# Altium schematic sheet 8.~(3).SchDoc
size 420 x 297 mm
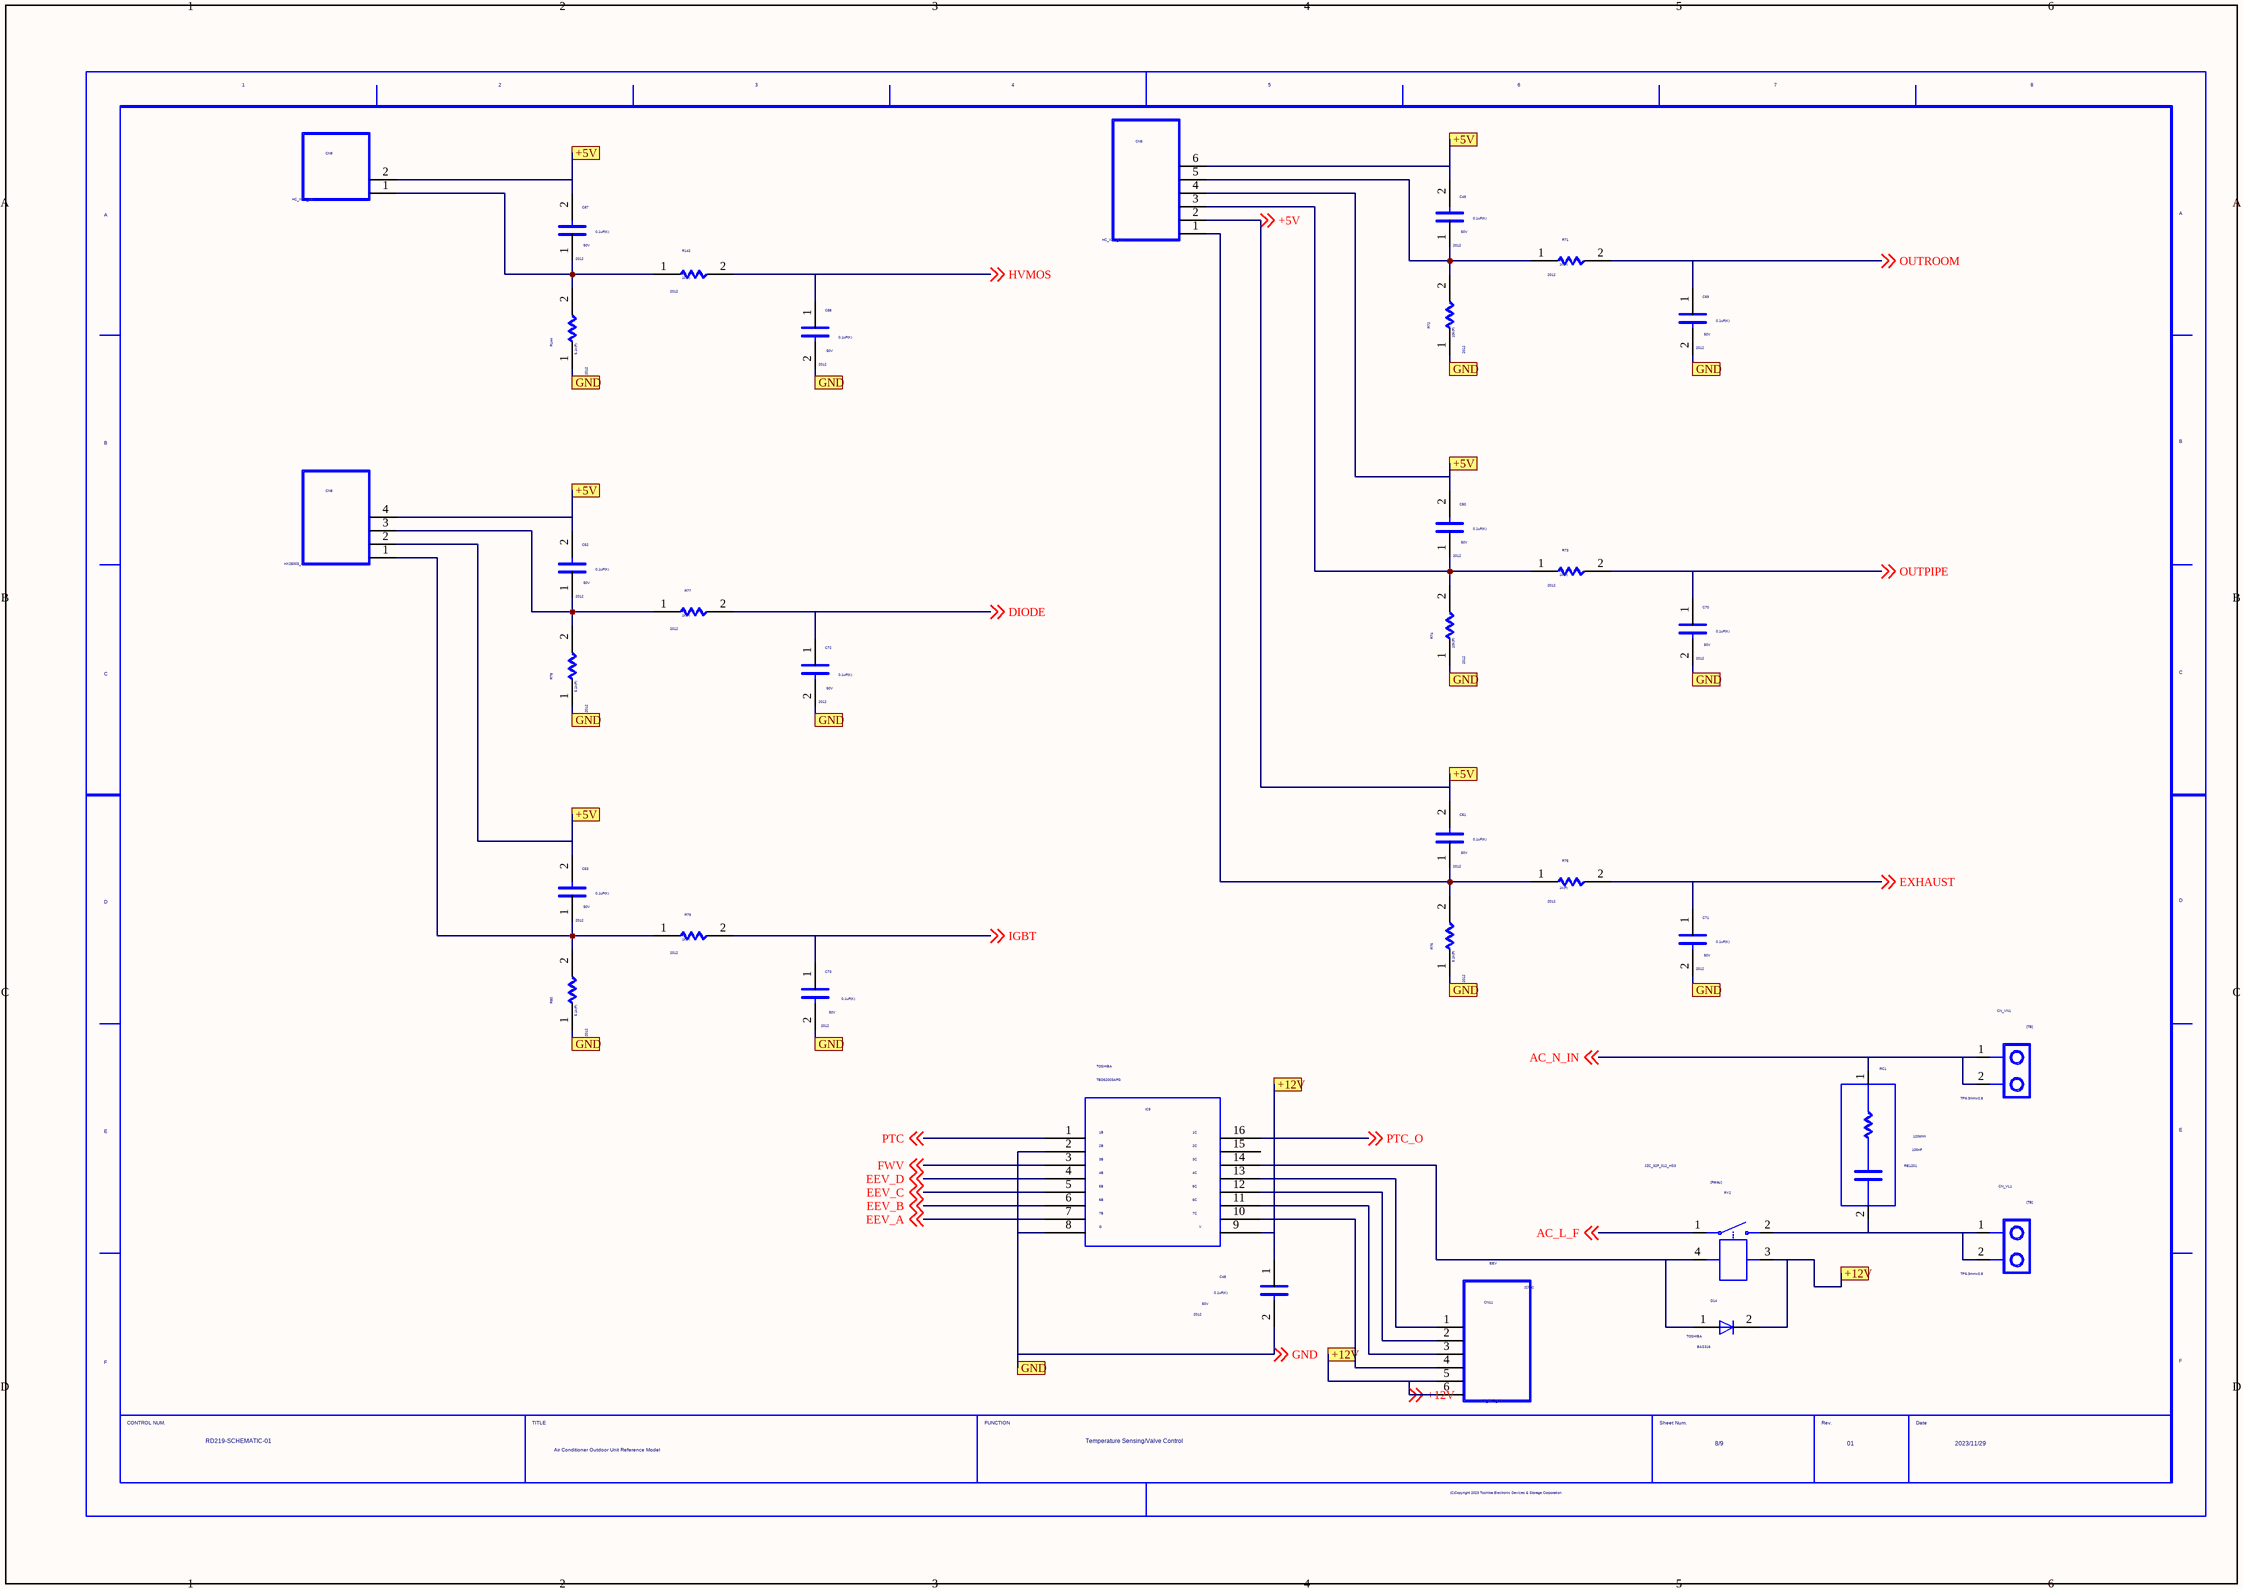
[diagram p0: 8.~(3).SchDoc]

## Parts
C48  SIZECODESMD: 2012  VAL2: 50V  VAL1: 0.1uF(K)  (hidden comment: C)
C49  SIZECODESMD: 2012  VAL2: 50V  VAL1: 0.1uF(K)  (hidden comment: C)
C50  SIZECODESMD: 2012  VAL2: 50V  VAL1: 0.1uF(K)  (hidden comment: C)
C51  SIZECODESMD: 2012  VAL2: 50V  VAL1: 0.1uF(K)  (hidden comment: C)
C52  SIZECODESMD: 2012  VAL2: 50V  VAL1: 0.1uF(K)  (hidden comment: C)
C53  SIZECODESMD: 2012  VAL2: 50V  VAL1: 0.1uF(K)  (hidden comment: C)
C69  SIZECODESMD: 2012  VAL2: 50V  VAL1: 0.1uF(K)  (hidden comment: C)
C70  SIZECODESMD: 2012  VAL2: 50V  VAL1: 0.1uF(K)  (hidden comment: C)
C71  SIZECODESMD: 2012  VAL2: 50V  VAL1: 0.1uF(K)  (hidden comment: C)
C72  SIZECODESMD: 2012  VAL2: 50V  VAL1: 0.1uF(K)  (hidden comment: C)
C73  SIZECODESMD: 2012  VAL2: 50V  VAL1: 0.1uF(K)  (hidden comment: C)
C87  SIZECODESMD: 2012  VAL2: 50V  VAL1: 0.1uF(K)  (hidden comment: C)
C88  SIZECODESMD: 2012  VAL2: 50V  VAL1: 0.1uF(K)  (hidden comment: C)
CN5  VAL3: HC_XHB_6A  (hidden comment: CN6Y)
CN8  VAL3: HX25003_4A  (hidden comment: CN4Y)
CN9  VAL3: HC_XHB_2A  (hidden comment: CN2Y)
CN11  VAL3: HC_XHB_6A  COMPCOMMENT: EEV  (hidden comment: CN6)
CN_VL1  COMPCOMMENT: TP6.3mmx0.8  (hidden comment: TB2A)
CN_VN1  COMPCOMMENT: TP6.3mmx0.8  (hidden comment: TB2A)
D14  USERCOMPTEXT3: TOSHIBA  VAL3: BAS316  (hidden comment: D_CUSTOM)
IC9  USERCOMPTEXT3: TOSHIBA  VAL1: TBD62003AFG  (hidden comment: TBD62003)
R71  SIZECODESMD: 2012  VAL1: 1k(F)  (hidden comment: R)
R72  SIZECODESMD: 2012  VAL1: 10k(F)  (hidden comment: R)
R73  SIZECODESMD: 2012  VAL1: 1k(F)  (hidden comment: R)
R74  SIZECODESMD: 2012  VAL1: 10k(F)  (hidden comment: R)
R75  SIZECODESMD: 2012  VAL1: 1k(F)  (hidden comment: R)
R76  SIZECODESMD: 2012  VAL1: 5.1k(F)  (hidden comment: R)
R77  SIZECODESMD: 2012  VAL1: 1k(F)  (hidden comment: R)
R78  SIZECODESMD: 2012  VAL1: 5.1k(F)  (hidden comment: R)
R79  SIZECODESMD: 2012  VAL1: 1k(F)  (hidden comment: R)
R80  SIZECODESMD: 2012  VAL1: 5.1k(F)  (hidden comment: R)
R142  SIZECODESMD: 2012  VAL1: 1k(F)  (hidden comment: R)
R144  SIZECODESMD: 2012  VAL1: 5.1k(F)  (hidden comment: R)
RC1  VAL2: 120ohm  VAL1: 100nF  VAL3: RE1201  (hidden comment: RC)
RY2  VAL1: JZC_32F_012_HS3  (hidden comment: SFK-112)
U?  DATE: 2023/11/29  TITLE: Air Conditioner Outdoor Unit / Reference Model  DRAWINGNUMBER: RD219-SCHEMATIC-01  SHEETNUMBER: 8/9  FUNCTION: Temperature Sensing/Valve Control  REVISION: 01  (hidden comment: WAKU_DEF100)

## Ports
+5V, +12V, GND

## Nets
+5V: C49.2 C50.2 C51.2 C52.2 C53.2 C87.2 CN5.2 CN5.4 CN5.6 CN8.2 CN8.4 CN9.2 ; off-sheet +5V, port +5V
AC_L_F: RY2.1 ; off-sheet AC_L_F
AC_N_IN: CN_VN1.1 CN_VN1.2 RC1.1 ; off-sheet AC_N_IN
DIODE: C72.1 R77.2 ; off-sheet DIODE
EEV_A: IC9.7 ; off-sheet EEV_A
EEV_B: IC9.6 ; off-sheet EEV_B
EEV_C: IC9.5 ; off-sheet EEV_C
EEV_D: IC9.4 ; off-sheet EEV_D
EXHAUST: C71.1 R75.2 ; off-sheet EXHAUST
FWV: IC9.3 ; off-sheet FWV
GND: C48.2 C69.2 C70.2 C71.2 C72.2 C73.2 C88.2 IC9.2 IC9.8 R72.1 R74.1 R76.1 R78.1 R80.1 R144.1 ; off-sheet GND, port GND
HVMOS: C88.1 R142.2 ; off-sheet HVMOS
IGBT: C73.1 R79.2 ; off-sheet IGBT
NetC49_1: C49.1 CN5.5 R71.1 R72.2
NetC50_1: C50.1 CN5.3 R73.1 R74.2
NetC51_1: C51.1 CN5.1 R75.1 R76.2
NetC52_1: C52.1 CN8.3 R77.1 R78.2
NetC53_1: C53.1 CN8.1 R79.1 R80.2
NetC87_1: C87.1 CN9.1 R142.1 R144.2
NetCN11_1: CN11.1 IC9.13
NetCN11_2: CN11.2 IC9.12
NetCN11_3: CN11.3 IC9.11
NetCN11_4: C48.1 CN11.4 CN11.5 CN11.6 D14.2 IC9.9 IC9.10 RY2.3 ; off-sheet +12V, port +12V  [also labelled +12V]
NetCN-VL1_1: CN_VL1.1 CN_VL1.2 RC1.2 RY2.2
NetD14_1: D14.1 IC9.14 RY2.4
OUTPIPE: C70.1 R73.2 ; off-sheet OUTPIPE
OUTROOM: C69.1 R71.2 ; off-sheet OUTROOM
PTC: IC9.1 ; off-sheet PTC
PTC_O: IC9.16 ; off-sheet PTC_O

Not connected (* = marked no-connect by the designer): IC9 15

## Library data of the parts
C48 = C_Dup1: OriginalSymbolOrigin: (2540,7620); VAL3: AC0805KRX7R9BB104
C49-C53 C69-C73 C87 C88 = C: OriginalSymbolOrigin: (2540,7620); VAL3: AC0805KRX7R9BB104
CN5 = CN6Y: SAVEAREA0: -8909,-546,28423,26783; TIME: 09:54:13; UPDATEUSER: w20165dm; SAVECOUNT: 1; OriginalSymbolOrigin: (2540,25400)
CN8 = CN4Y: SAVEAREA0: -5115,-437,24748,21425; TIME: 09:53:19; UPDATEUSER: w20165dm; SAVECOUNT: 1; OriginalSymbolOrigin: (2540,20320)
CN9 = CN2Y: SAVEAREA0: -6573,-310,26384,16086; TIME: 09:52:32; UPDATEUSER: w20165dm; SAVECOUNT: 1; OriginalSymbolOrigin: (2540,15240); COMPCOMMENT: TEMP3
CN11 = CN6: OriginalSymbolOrigin: (2540,25400)
CN_VL1 CN_VN1 = TB2A: SAVEAREA0: -6249,-369,19007,18120; TIME: 11:16:32; UPDATEUSER: w20165dm; SAVECOUNT: 1; OriginalSymbolOrigin: (2540,12700); VAL3: DJ6110-6.3x0.8; COMP: TP
D14 = D_CUSTOM: SAVEAREA0: -1668,-97,14265,7829; SAVECOUNT: 4; TIME: 14:49:55; UPDATEUSER: w20165dm; UPDATETIME: 16:47:49; OriginalSymbolOrigin: (5080,5080)
IC9 = TBD62003: SAVECOUNT: 34; SAVEAREA0: -8546,-383,48557,34032; TIME: 11:13:04; UPDATEUSER: w20165dm; UPDATETIME: 19:36:15; OriginalSymbolOrigin: (7620,30480)
R71 R75 = R: OriginalSymbolOrigin: (5080,5080); VAL3: AC0805FR-071KL; VAL2: 125mW; COMP: AC0805FR_071KL
R72 R74 = R: OriginalSymbolOrigin: (5080,5080); VAL3: AC0805FR-0710KL; VAL2: 125mW; COMP: AC08005FR_0710KL
R73 R77 R79 = R: OriginalSymbolOrigin: (5080,5080); VAL2: 125mW; VAL3: AC0805FR-071KL; COMP: AC0805FR_071KL
R76 = R: OriginalSymbolOrigin: (5080,5080); COMP: AC0805FR_075K1L; VAL3: AC0805FR-075K1L; VAL2: 125mW
R78 = R: OriginalSymbolOrigin: (5080,5080); VAL2: 125mW; VAL3: AC0805FR-075K1L; COMP: AC0805FR_075K1L
R80 = R: OriginalSymbolOrigin: (5080,5080); VAL3: AC0805FR-075K1L; VAL2: 125mW; COMP: AC0805FR_075K1L
R142 = R: OriginalSymbolOrigin: (5080,5080); VAL3: AC0805FR_071KL; VAL2: 125mW
R144 = R: OriginalSymbolOrigin: (5080,5080); VAL3: AC0805FR_075K1L; VAL2: 125mW
RC1 = RC: SAVEAREA0: -17024,-284,34362,28697; TIME: 17:42:57; UPDATEUSER: w20165dm; UPDATETIME: 17:46:02; SAVECOUNT: 2; OriginalSymbolOrigin: (2540,25400)
RY2 = SFK-112: SAVEAREA0: -13231,-231,28521,20540; TIME: 14:06:16; UPDATEUSER: w20165dm; UPDATETIME: 17:57:42; SAVECOUNT: 24; OriginalSymbolOrigin: (2540,12700)
U? = WAKU_DEF100: PLOTTIME: HH:MM; SAVEAREA0: -45080,-4508,463680,304612; TIME: 11:16:27; UPDATEUSER: sptcae13; UPDATETIME: 08:19:31; SAVECOUNT: 8; OriginalSymbolOrigin: (10160,284480)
